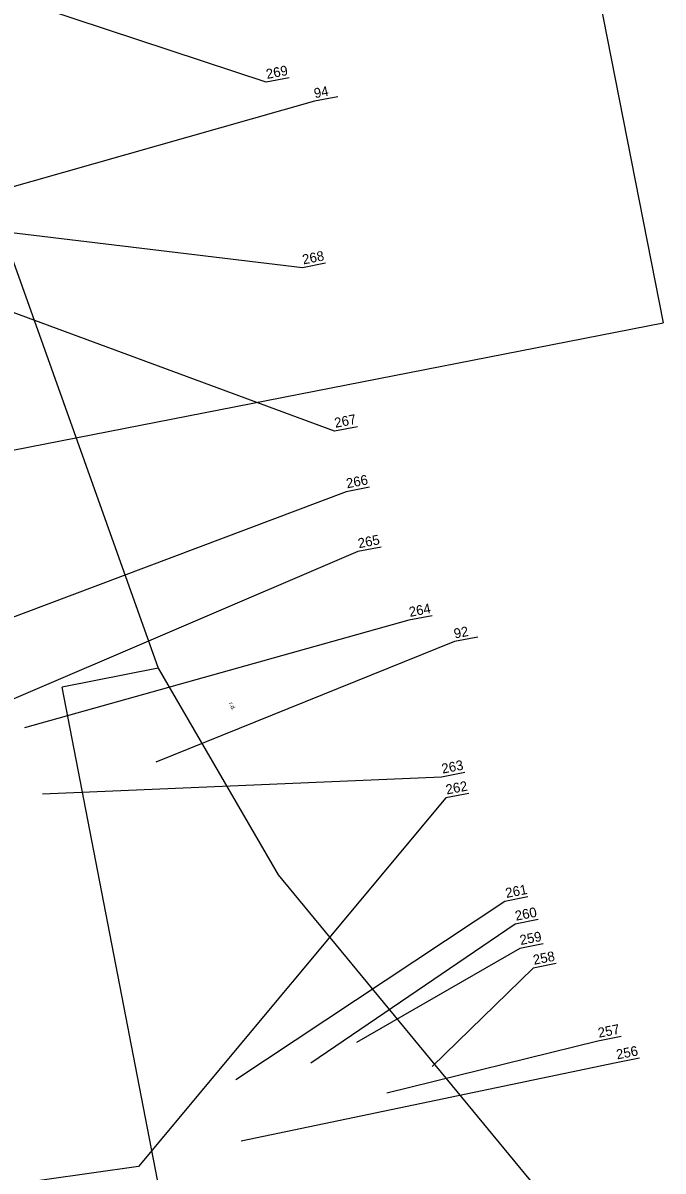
# Model space of a CAD drawing. Extents: x -545967 to -545044, y -1122650 to -1118491.
# Drawn here: x -545636.3 to -545513.8, y -1119477.8 to -1119258 of the extents above; entities that cross this region are included whole.
import ezdxf

# ---------------------------------------------------------------- set-up
doc = ezdxf.new("R2010")
doc.units = 0
for name, color, linetype in [('osvětlené plochy-hodnota-obrys', 7, 'Continuous'), ('so180602', 7, 'Continuous'), ('Vrstva 10', 7, 'Continuous'), ('Vrstva 63', 7, 'Continuous')]:
    doc.layers.add(name, color=color, linetype=linetype)

msp = doc.modelspace()

# ---------------------------------------------------------------- linework, layer by layer
at = {"layer": 'osvětlené plochy-hodnota-obrys'}
for points in [[(-545700.79, -1119127.99), (-545610.46, -1119381.57), (-545628.87, -1119385.18)], [(-545610.46, -1119381.57), (-545587.49, -1119421.11), (-545524.22, -1119497.93), (-545520.97, -1119506.47)], [(-545584.85, -1119581.02), (-545603.39, -1119516.8), (-545628.87, -1119385.18)]]:
    msp.add_lwpolyline(points, dxfattribs=at)
at = {"layer": 'Vrstva 10'}
for p in [(-545675.17, -1118491.08), (-545805.3, -1119372.48)]:
    msp.add_line(p, (-545513.83, -1119315.44), dxfattribs=at)
at = {"layer": 'Vrstva 63'}
for p, q in [((-545589.82, -1119269.35), (-545695.29, -1119234.41)), ((-545585.37, -1119268.49), (-545589.82, -1119269.35)), ((-545585.37, -1119268.49), (-545589.82, -1119269.35)), ((-545585.37, -1119268.49), (-545589.82, -1119269.35)), ((-545580.52, -1119272.98), (-545640.7, -1119290.06)), ((-545576.08, -1119272.12), (-545580.52, -1119272.98)), ((-545582.87, -1119304.87), (-545670.89, -1119294.27)), ((-545576.74, -1119336.16), (-545683.58, -1119296.75)), ((-545578.42, -1119304.01), (-545582.87, -1119304.87)), ((-545578.42, -1119304.01), (-545582.87, -1119304.87)), ((-545578.42, -1119304.01), (-545582.87, -1119304.87)), ((-545572.3, -1119335.3), (-545576.74, -1119336.16)), ((-545572.3, -1119335.3), (-545576.74, -1119336.16)), ((-545572.3, -1119335.3), (-545576.74, -1119336.16)), ((-545574.48, -1119347.75), (-545666.7, -1119382.49)), ((-545570.03, -1119346.88), (-545574.48, -1119347.75)), ((-545570.03, -1119346.88), (-545574.48, -1119347.75)), ((-545570.03, -1119346.88), (-545574.48, -1119347.75)), ((-545572.23, -1119359.23), (-545663.68, -1119398.34)), ((-545567.79, -1119358.36), (-545572.23, -1119359.23)), ((-545567.79, -1119358.36), (-545572.23, -1119359.23)), ((-545567.79, -1119358.36), (-545572.23, -1119359.23)), ((-545562.46, -1119372.38), (-545636.05, -1119392.97)), ((-545558.02, -1119371.51), (-545562.46, -1119372.38)), ((-545558.02, -1119371.51), (-545562.46, -1119372.38)), ((-545558.02, -1119371.51), (-545562.46, -1119372.38)), ((-545553.75, -1119376.46), (-545610.92, -1119399.53)), ((-545549.31, -1119375.6), (-545553.75, -1119376.46)), ((-545551.77, -1119401.52), (-545556.21, -1119402.39)), ((-545551.77, -1119401.52), (-545556.21, -1119402.39)), ((-545551.77, -1119401.52), (-545556.21, -1119402.39)), ((-545556.21, -1119402.39), (-545632.6, -1119405.65)), ((-545550.99, -1119405.53), (-545555.43, -1119406.39)), ((-545550.99, -1119405.53), (-545555.43, -1119406.39)), ((-545550.99, -1119405.53), (-545555.43, -1119406.39)), ((-545555.43, -1119406.39), (-545614.24, -1119476.95)), ((-545539.69, -1119425.35), (-545544.13, -1119426.22)), ((-545539.69, -1119425.35), (-545544.13, -1119426.22)), ((-545539.69, -1119425.35), (-545544.13, -1119426.22)), ((-545544.13, -1119426.22), (-545595.62, -1119460.4)), ((-545537.71, -1119429.69), (-545542.16, -1119430.55)), ((-545537.71, -1119429.69), (-545542.16, -1119430.55)), ((-545537.71, -1119429.69), (-545542.16, -1119430.55)), ((-545542.16, -1119430.55), (-545581.23, -1119457.16)), ((-545536.8, -1119434.35), (-545541.25, -1119435.21)), ((-545536.8, -1119434.35), (-545541.25, -1119435.21)), ((-545536.8, -1119434.35), (-545541.25, -1119435.21)), ((-545541.25, -1119435.21), (-545572.5, -1119453.23)), ((-545538.71, -1119438.99), (-545558.04, -1119457.8)), ((-545534.26, -1119438.12), (-545538.71, -1119438.99)), ((-545534.26, -1119438.12), (-545538.71, -1119438.99)), ((-545534.26, -1119438.12), (-545538.71, -1119438.99)), ((-545521.86, -1119452.11), (-545526.3, -1119452.97)), ((-545521.86, -1119452.11), (-545526.3, -1119452.97)), ((-545521.86, -1119452.11), (-545526.3, -1119452.97)), ((-545526.3, -1119452.97), (-545566.69, -1119462.96)), ((-545518.35, -1119456.26), (-545522.79, -1119457.12)), ((-545518.35, -1119456.26), (-545522.79, -1119457.12)), ((-545518.35, -1119456.26), (-545522.79, -1119457.12)), ((-545522.79, -1119457.12), (-545594.6, -1119472.11)), ((-545614.24, -1119476.95), (-545705.2, -1119490))]:
    msp.add_line(p, q, dxfattribs=at)

# ---------------------------------------------------------------- texts
at = {"layer": 'so180602'}
for s, p in [('269', (-545589.63, -1119268.72)), ('94', (-545580.46, -1119272.4)), ('268', (-545582.68, -1119304.23)), ('267', (-545576.54, -1119335.52)), ('266', (-545574.29, -1119347.11)), ('265', (-545572.04, -1119358.59)), ('264', (-545562.27, -1119371.74)), ('92', (-545553.68, -1119375.88)), ('263', (-545556.03, -1119401.75)), ('262', (-545555.23, -1119405.75)), ('261', (-545543.8, -1119425.56)), ('260', (-545541.97, -1119429.92)), ('259', (-545541.06, -1119434.57)), ('258', (-545538.52, -1119438.35)), ('257', (-545526.1, -1119452.33)), ('256', (-545522.6, -1119456.48))]:
    msp.add_text(s, height=1.875, rotation=10.9955, dxfattribs=at).set_placement(p)
at = {"layer": 'Vrstva 63'}
msp.add_text('r.d.', height=0.8, rotation=293.9153, dxfattribs=at).set_placement((-545596.94, -1119388.25))

doc.saveas('drawing.dxf')
